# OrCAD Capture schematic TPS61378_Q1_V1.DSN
size C; title: TPS61378 Q1 FPWM model; rev: V1
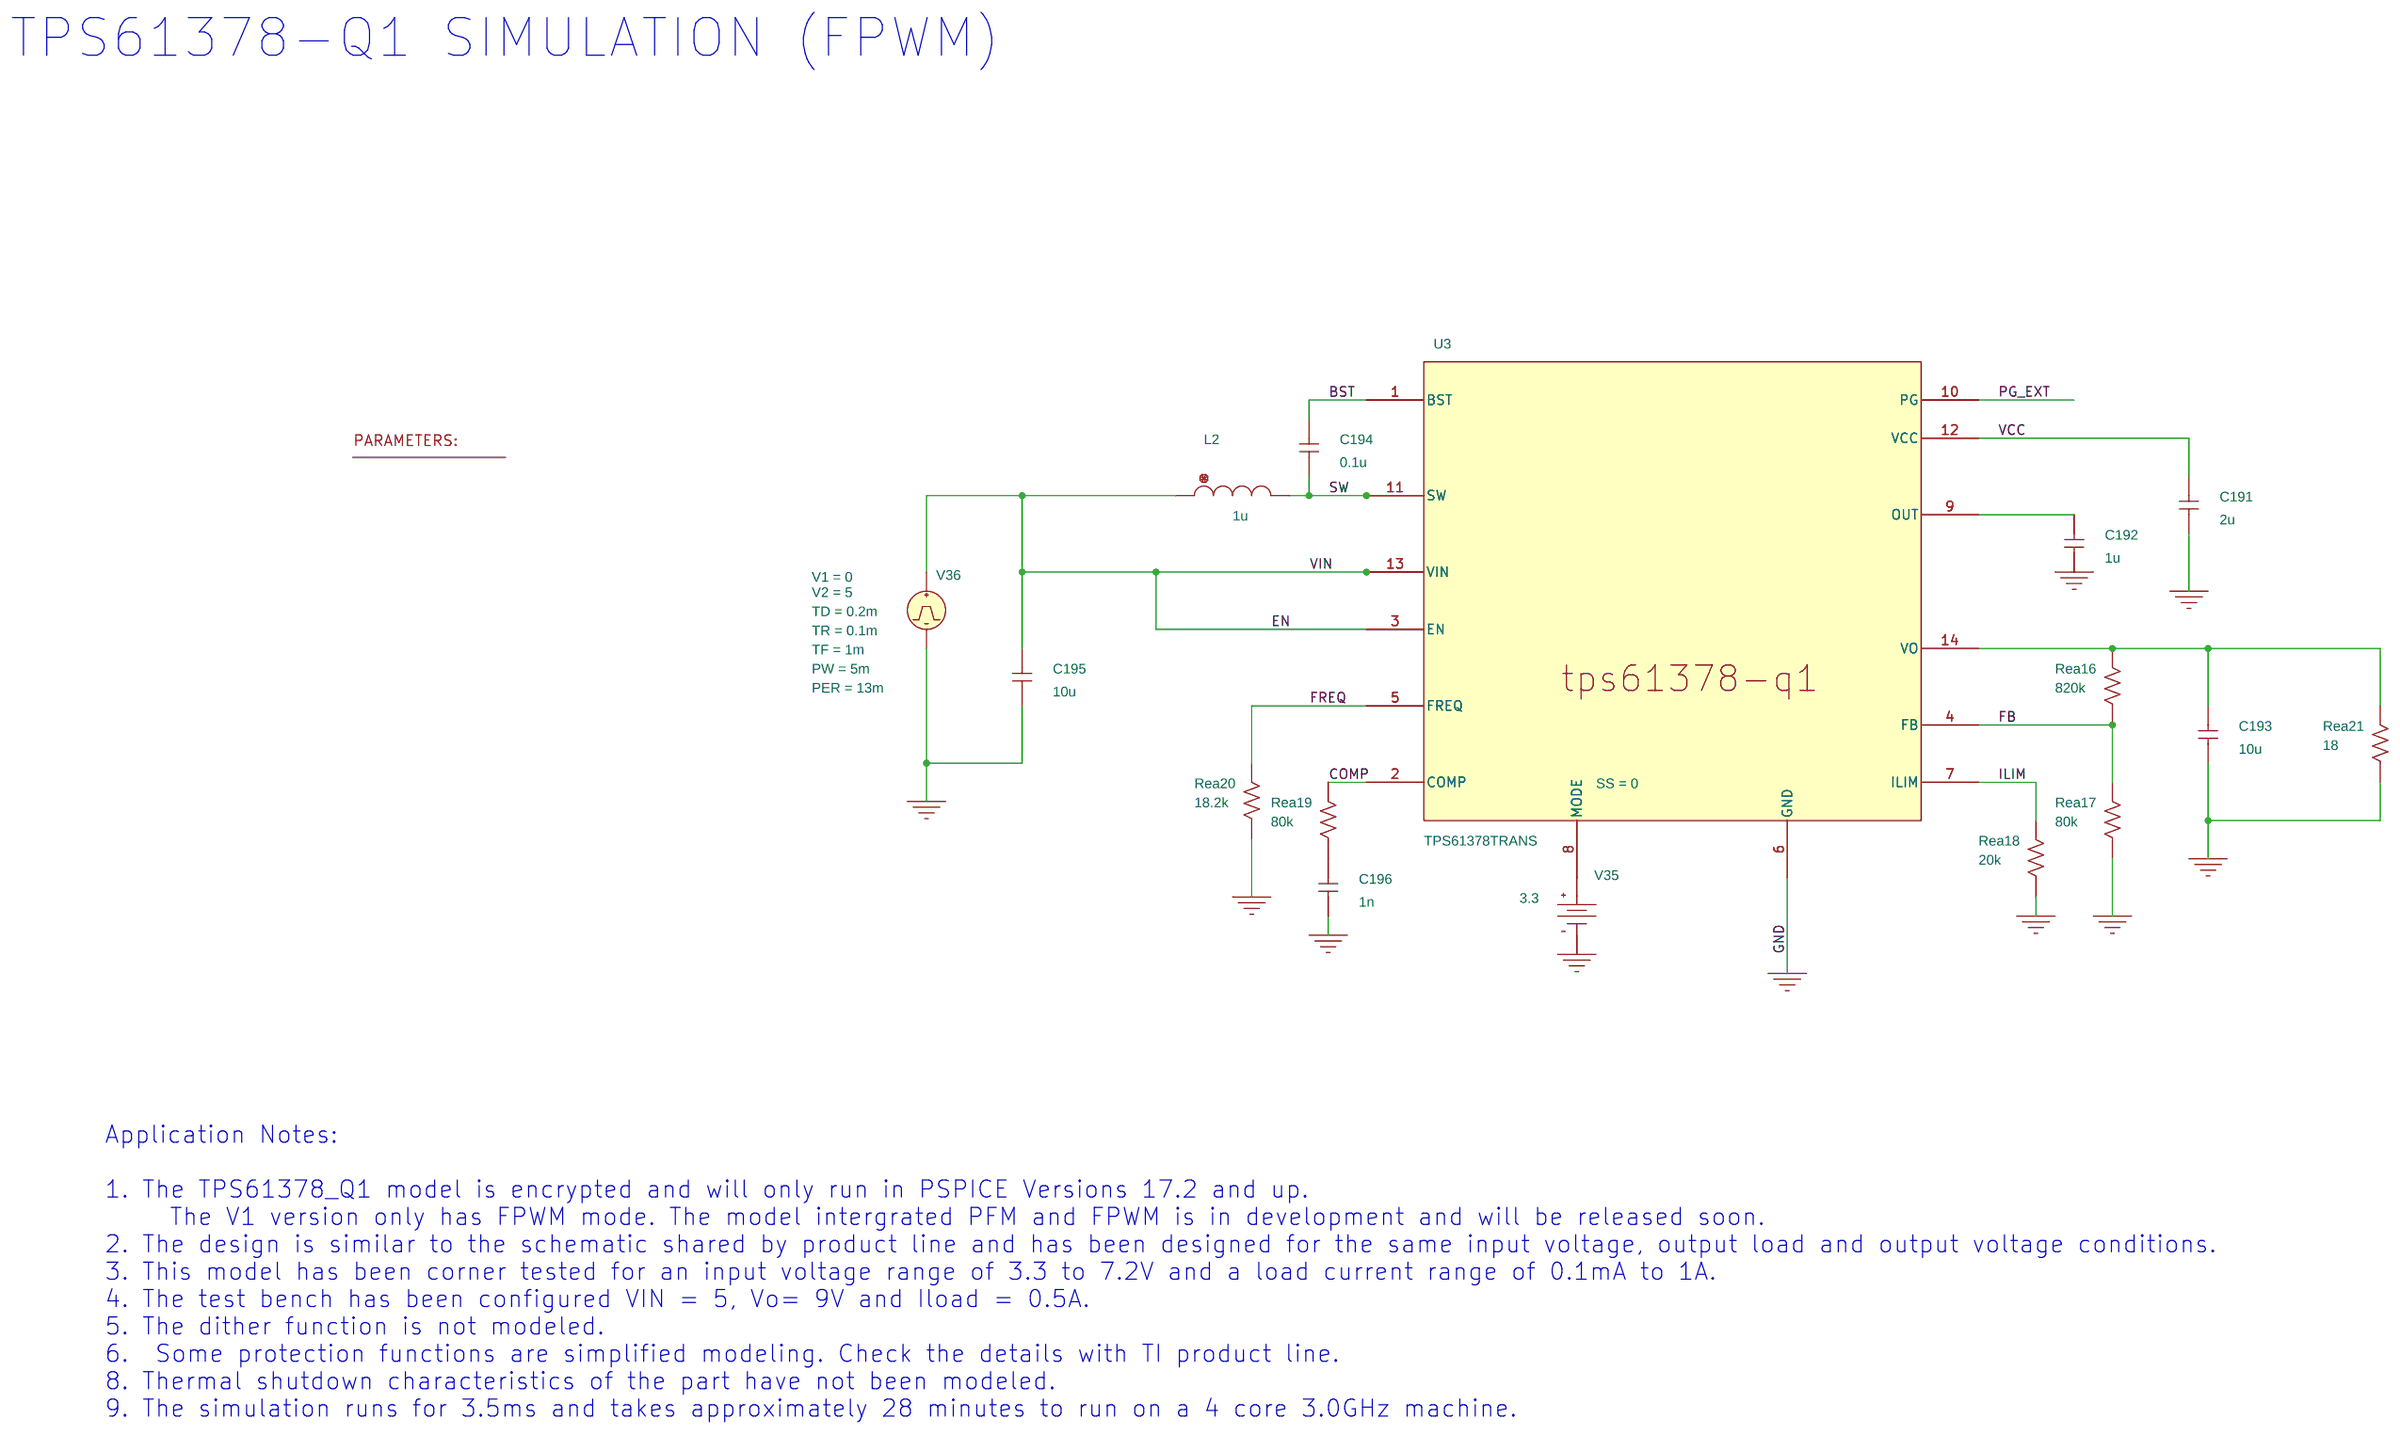
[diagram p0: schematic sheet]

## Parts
1  PARAM
C191  2u  [cap196]
C192  1u  [cap196]
C193  10u  [cap196]
C194  0.1u  [cap196]
C195  10u  [cap196]
C196  1n  [cap196]
L2  1u  [DISC350x175LS200x100034]
Rea16  820k  [AX/RC05]
Rea17  80k  [AX/RC05]
Rea18  20k  [AX/RC05]
Rea19  80k  [AX/RC05]
Rea20  18.2k  [AX/RC05]
Rea21  18  [AX/RC05]
U3  TPS61378TRANS
V35  VDC
V36  VPULSE

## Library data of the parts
1 = PARAM: COUT: 0.75; Fast_Start: 0; IOUT: 2; SS: 0; VIN: 5; VOUT: 16
C191-C196 = C
L2 = L
Rea16-Rea21 = R
U3 = TPS61378TRANS_4: FAST_STARTUP: 0; SS: 0
V35 = VDC: DC: 3.3
V36 = VPULSE: AC: 0; AppProp: Pulse$Voltage$1$-1; DC: 0; PER: 13m; PW: 5m; TD: 0.2m; TF: 1m; TR: 0.1m; V1: 0; V2: 5

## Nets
VCC: C191.2 U3.12(VCC)
0: C191.1 C192.1 C193.1 C195.1 C196.1 Rea17.1 Rea18.1 Rea20.1 Rea21.1 U3.6(GND) V35.1(-) V36.2(-)
BST: C194.2 U3.1(BST)
COMP: Rea19.2 U3.2(COMP)
EN: C195.2 L2.1 U3.3(EN) U3.13(VIN) V36.1(+)
FB: Rea16.1 Rea17.2 U3.4(FB)
FREQ: Rea20.2 U3.5(FREQ)
ILIM: Rea18.2 U3.7(ILIM)
PG_EXT: U3.10(PG)
SW: C194.1 L2.2 U3.11(SW)
N20033: C192.2 U3.9(OUT)
N20163: C193.2 Rea16.2 Rea21.2 U3.14(VO)
N21538: C196.2 Rea19.1
N21539: U3.8(MODE) V35.0(+)

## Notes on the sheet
- TPS61378-Q1 SIMULATION (FPWM)
- Application Notes:
  1. The TPS61378_Q1 model is encrypted and will only run in PSPICE Versions 17.2 and up.
       The V1 version only has FPWM mode. The model intergrated PFM and FPWM is in development and will be released soon.
  2. The design is similar to the schematic shared by product line and has been designed for the same input voltage, output load and output voltage conditions.
  3. This model has been corner tested for an input voltage range of 3.3 to 7.2V and a load current range of 0.1mA to 1A.
  4. The test bench has been configured VIN = 5, Vo= 9V and Iload = 0.5A.
  5. The dither function is not modeled.
  6.  Some protection functions are simplified modeling. Check the details with TI product line.
  8. Thermal shutdown characteristics of the part have not been modeled.
  9. The simulation runs for 3.5ms and takes approximately 28 minutes to run on a 4 core 3.0GHz machine.
